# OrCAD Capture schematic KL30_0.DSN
size D
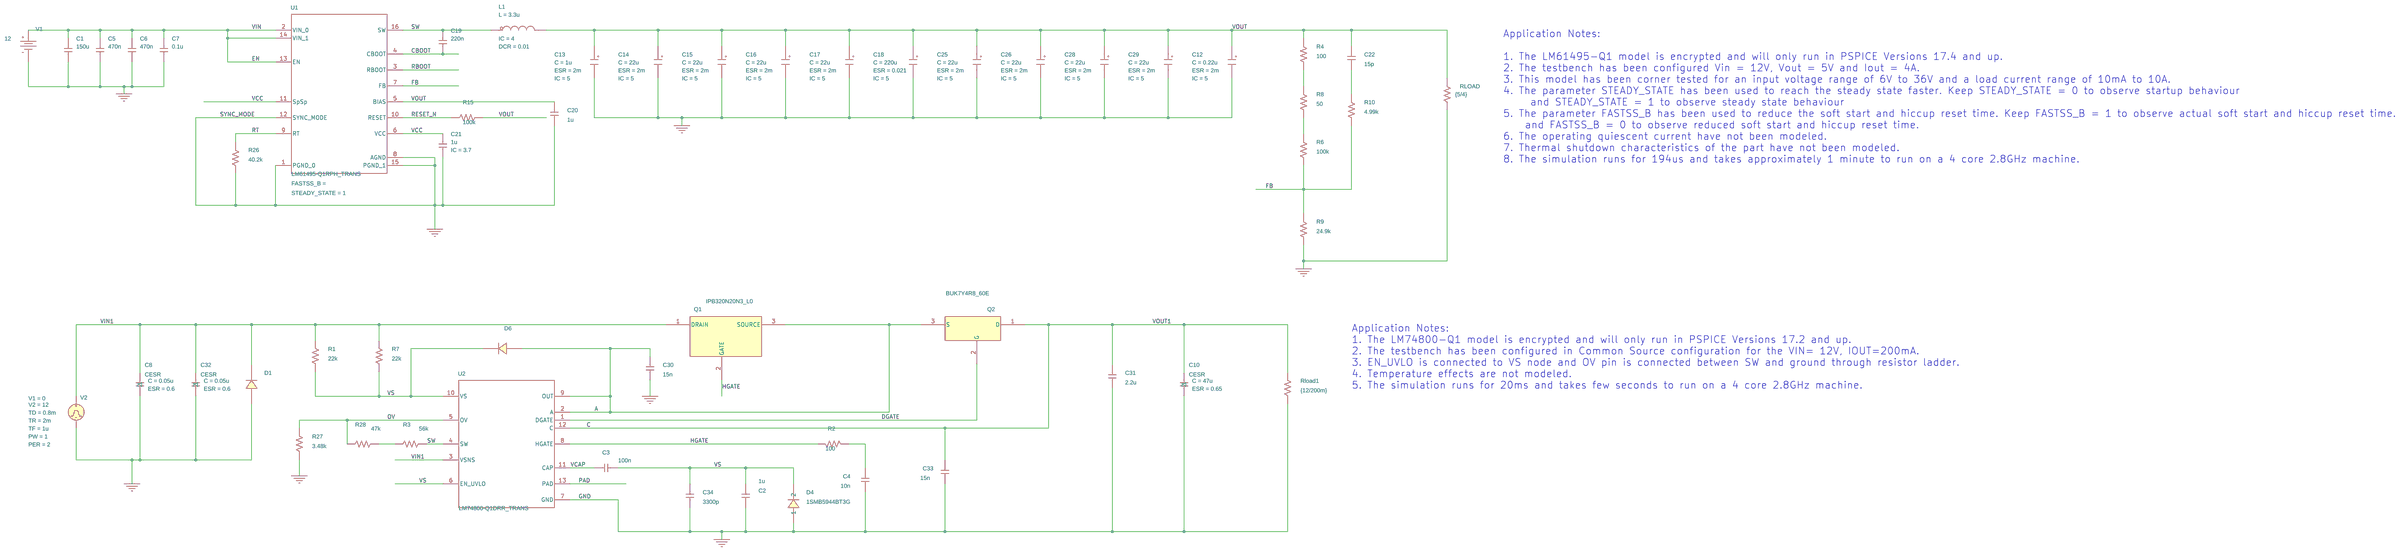
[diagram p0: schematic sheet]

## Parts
C1  150u  [RAD/CK05]
C2  1u  [RAD/CK05]
C3  100n  [RAD/CK05]
C4  10n  [RAD/CK05]
C5  470n  [RAD/CK05]
C6  470n  [RAD/CK05]
C7  0.1u  [RAD/CK05]
C8  CESR
C10  CESR
C12  CESR
C13  CESR
C14  CESR
C15  CESR
C16  CESR
C17  CESR
C18  CESR
C19  220n  [RAD/CK05]
C20  1u  [RAD/CK05]
C21  1u  [RAD/CK05]
C22  15p  [RAD/CK05]
C25  CESR
C26  CESR
C28  CESR
C29  CESR
C30  15n  [RAD/CK05]
C31  2.2u  [RAD/CK05]
C32  CESR
C33  15n  [RAD/CK05]
C34  3300p  [RAD/CK05]
D1  SMBJ33A
D4  1SMB5944BT3G
D6  1N4148WS
L1  LDCR
Q1  IPB320N20N3_L0
Q2  BUK7Y4R8_60E
R1  22k  [AX/RC05]
R2  100  [AX/RC05]
R3  56k  [AX/RC05]
R4  100  [AX/RC05]
R6  100k  [AX/RC05]
R7  22k  [AX/RC05]
R8  50  [AX/RC05]
R9  24.9k  [AX/RC05]
R10  4.99k  [AX/RC05]
R15  100k  [AX/RC05]
R26  40.2k  [AX/RC05]
R27  3.48k  [AX/RC05]
R28  47k  [AX/RC05]
RLOAD  {5/4}  [AX/RC05]
Rload1  {12/200m}  [AX/RC05]
U1  LM61495-Q1RPH_TRANS  [RPH0016A]
U2  LM74800-Q1DRR_TRANS  [DRR0012E]
V1  VDC
V2  VPULSE

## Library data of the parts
C1-C7 C19 C20 C22 C30 C31 C33 C34 = C
C8 = CESR_2: C: 0.05u; ESL: 0; ESR: 0.6; PSpiceTemplate: X^@REFDES %1 %2 @MODEL PARAMS: ?C|C=@C||C=10U| ?ESR|ESR=@ESR||ESR=2M| ?IC|IC=@IC||IC=0|
C10 = CESR: C: 47u; ESL: 0; ESR: 0.65; PSpiceTemplate: X^@REFDES %1 %2 @MODEL PARAMS: ?C|C=@C||C=10U| ?ESR|ESR=@ESR||ESR=2M| ?IC|IC=@IC||IC=0|
C12 = CESR_0: C: 0.22u; ESR: 2m; IC: 5; PSpiceTemplate: X^@REFDES %IN %OUT @MODEL PARAMS:  ?C|C=@C||C=100u|  ?ESR|ESR=@ESR||ESR=0.01| ?X|X=@X||X=2|  ?IC|IC=@IC||IC=2|; X: 1
C13 = CESR_0: C: 1u; ESR: 2m; IC: 5; PSpiceTemplate: X^@REFDES %IN %OUT @MODEL PARAMS:  ?C|C=@C||C=100u|  ?ESR|ESR=@ESR||ESR=0.01| ?X|X=@X||X=2|  ?IC|IC=@IC||IC=2|; X: 1
C14-C17 C25 C26 C28 C29 = CESR_0: C: 22u; ESR: 2m; IC: 5; PSpiceTemplate: X^@REFDES %IN %OUT @MODEL PARAMS:  ?C|C=@C||C=100u|  ?ESR|ESR=@ESR||ESR=0.01| ?X|X=@X||X=2|  ?IC|IC=@IC||IC=2|; X: 1
C18 = CESR_0: C: 220u; ESR: 0.021; IC: 5; PSpiceTemplate: X^@REFDES %IN %OUT @MODEL PARAMS:  ?C|C=@C||C=100u|  ?ESR|ESR=@ESR||ESR=0.01| ?X|X=@X||X=2|  ?IC|IC=@IC||IC=2|; X: 1
C21 = C: IC: 3.7
C32 = CESR_1: C: 0.05u; ESL: 0; ESR: 0.6; PSpiceTemplate: X^@REFDES %1 %2 @MODEL PARAMS: ?C|C=@C||C=10U| ?ESR|ESR=@ESR||ESR=2M| ?IC|IC=@IC||IC=0|
D1 = SMBJ33A
D4 = 1SMB5944BT3G
D6 = 1N4148WS
L1 = LDCR_0: DCR: 0.01; IC: 4; L: 3.3u; PSpiceTemplate: X^@REFDES %IN %OUT @MODEL PARAMS:  ?L|L=@L||L=1u|  ?DCR|DCR=@DCR||DCR=0.01| ?IC|IC=@IC||IC=0|
Q1 = IPB320N20N3_L0
Q2 = BUK7Y4R8_60E
R1-R3 R7 R27 R28 Rload1 = R
R4 R6 R8-R10 R15 R26 RLOAD = r
U1 = LM61495-Q1RPH_TRANS: STEADY_STATE: 1
U2 = LM74800-Q1DRR_TRANS
V1 = VDC: DC: 12
V2 = VPULSE: PER: 2; PW: 1; TD: 0.8m; TF: 1u; TR: 2m; V1: 0; V2: 12

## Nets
VCC: C21.1 U1.6(VCC) U1.11(SpSp)
VIN1: C8.1 C32.1 D1.1(C) Q1.1(DRAIN) R1.2 R7.2 U2.3(VSNS) V2.1(+)
0: C1.2 C2.2 C4.1 C5.2 C6.2 C7.2 C8.2 C10.2 C12.2(OUT) C13.2(OUT) C14.2(OUT) C15.2(OUT) C16.2(OUT) C17.2(OUT) C18.2(OUT) C20.2 C21.2 C25.2(OUT) C26.2(OUT) C28.2(OUT) C29.2(OUT) C30.1 C31.1 C32.2 C33.1 C34.1 D1.2(A) D4.1 R9.2 R26.2 R27.1 RLOAD.2 Rload1.1 U1.1(PGND_0) U1.8(AGND) U1.12(SYNC_MODE) U1.15(PGND_1) U2.7(GND) V1.1(-) V2.2(-)
A: C30.2 D6.2(A) Q1.3(SOURCE) Q2.3(S) U2.2(A) U2.9(OUT)
C: C10.1 C31.2 C33.2 Q2.1(D) Rload1.2 U2.12(C)
CBOOT: C19.2 U1.4(CBOOT)
DGATE: Q2.2(G) U2.1(DGATE)
EN: C1.1 C5.1 C6.1 C7.1 U1.2(VIN_0) U1.13(EN) U1.14(VIN_1) V1.0(+)
FB: R6.2 R9.1 R10.2 U1.7(FB)
HGATE: Q1.2(GATE) R2.2 U2.8(HGATE)
OV: R27.2 R28.2 U2.5(OV)
PAD: U2.13(PAD)
RBOOT: U1.3(RBOOT)
RESET_N: R15.1 U1.10(RESET)
RT: R26.1 U1.9(RT)
SW: C19.1 L1.1(IN) R3.1 U1.16(SW) U2.4(SW)
VCAP: C3.1 U2.11(CAP)
VOUT: C12.1(IN) C13.1(IN) C14.1(IN) C15.1(IN) C16.1(IN) C17.1(IN) C18.1(IN) C20.1 C22.1 C25.1(IN) C26.1(IN) C28.1(IN) C29.1(IN) L1.3(OUT) R4.1 R15.2 RLOAD.1 U1.5(BIAS)
VS: C2.1 C3.2 C34.2 D4.2 D6.1(C) R1.1 R7.1 U2.6(EN_UVLO) U2.10(VS)
N16770964: R4.2 R8.1
N16770968: C22.2 R10.1
N16771238: R6.1 R8.2
N16773427: R3.2 R28.1
N16773449: C4.2 R2.1

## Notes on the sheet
- Application Notes:
  1. The LM61495-Q1 model is encrypted and will only run in PSPICE Versions 17.4 and up.
  2. The testbench has been configured Vin = 12V, Vout = 5V and Iout = 4A.
  3. This model has been corner tested for an input voltage range of 6V to 36V and a load current range of 10mA to 10A.
  4. The parameter STEADY_STATE has been used to reach the steady state faster. Keep STEADY_STATE = 0 to observe startup behaviour
       and STEADY_STATE = 1 to observe steady state behaviour
  5. The parameter FASTSS_B has been used to reduce the soft start and hiccup reset time. Keep FASTSS_B = 1 to observe actual soft start and hiccup reset time.
      and FASTSS_B = 0 to observe reduced soft start and hiccup reset time.
  6. The operating quiescent current have not been modeled.
  7. Thermal shutdown characteristics of the part have not been modeled.
  8. The simulation runs for 194us and takes approximately 1 minute to run on a 4 core 2.8GHz machine.
- Application Notes:
  1. The LM74800-Q1 model is encrypted and will only run in PSPICE Versions 17.2 and up.
  2. The testbench has been configured in Common Source configuration for the VIN= 12V, IOUT=200mA.
  3. EN_UVLO is connected to VS node and OV pin is connected between SW and ground through resistor ladder.
  4. Temperature effects are not modeled.
  5. The simulation runs for 20ms and takes few seconds to run on a 4 core 2.8GHz machine.
